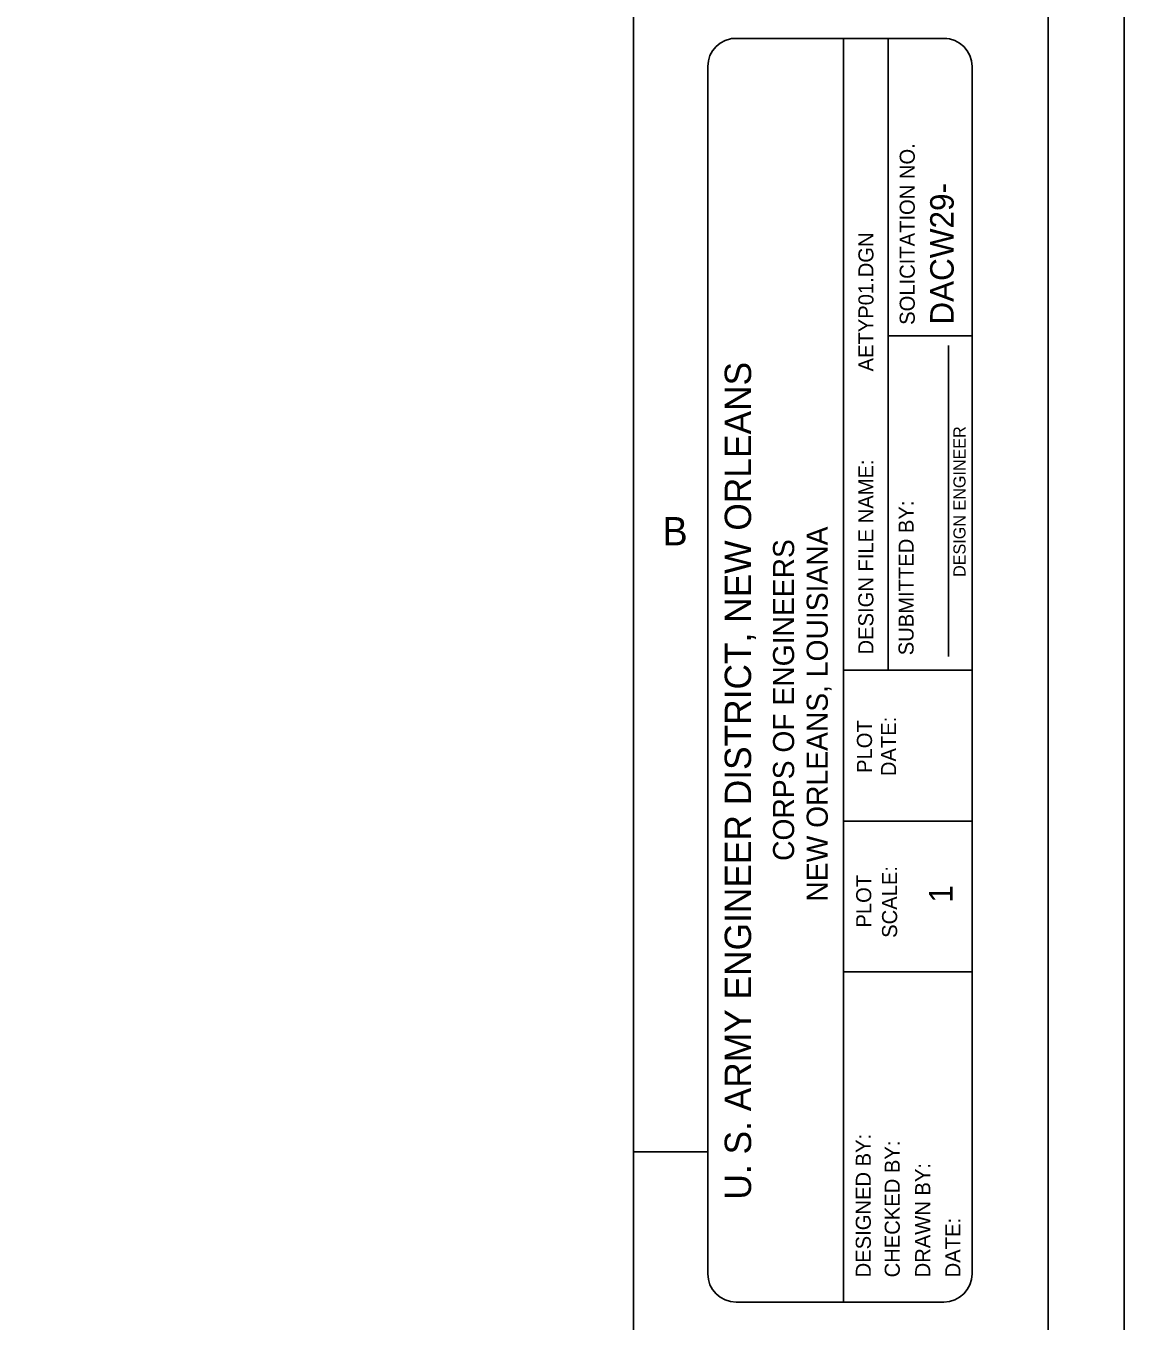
# Model space of a CAD drawing. Extents: x 44742.55 to 44745.38, y 44738.95 to 44741.13.
# Drawn here: x 44744.913 to 44745.38, y 44739.437 to 44739.989 of the extents above; entities that cross this region are included whole.
import ezdxf

# ---------------------------------------------------------------- set-up
doc = ezdxf.new("R2010")
doc.units = 0
for name, color, linetype in [('Level 1', 7, 'Continuous'), ('Level 10', 7, 'Continuous'), ('Level 2', 7, 'Continuous'), ('Level 7', 7, 'Continuous'), ('Level 9', 7, 'Continuous')]:
    doc.layers.add(name, color=color, linetype=linetype)

msp = doc.modelspace()

# ---------------------------------------------------------------- linework, layer by layer
at = {"layer": 'Level 1'}
for p, q in [((44745.30484, 44739.98338), (44745.21308, 44739.98338)), ((44745.26089, 44739.98338), (44745.26089, 44739.44515))]:
    msp.add_line(p, q, dxfattribs=at)
msp.add_lwpolyline([(44742.55302, 44741.13232), (44745.38041, 44741.13232), (44745.38041, 44738.94702), (44742.55302, 44738.94702)], close=True, dxfattribs=at)
for points in [[(44745.30359, 44739.98338), (44745.21511, 44739.98338)], [(44745.20306, 44739.4572), (44745.20306, 44739.97133)], [(44745.31564, 44739.4572), (44745.31564, 44739.97133)], [(44745.21511, 44739.44515), (44745.30359, 44739.44515)]]:
    msp.add_lwpolyline(points, dxfattribs=at)
for centre, start, end in [((44745.21511, 44739.97133), 90, 180), ((44745.30359, 44739.97133), 0, 90), ((44745.21511, 44739.4572), 180, 270), ((44745.30359, 44739.4572), 270, 0)]:
    msp.add_arc(centre, 0.01205, start, end, dxfattribs=at)
at = {"layer": 'Level 10'}
msp.add_line((44745.17144, 44739.50915), (44745.20306, 44739.50915), dxfattribs=at)
at = {"layer": 'Level 2'}
for p, q in [((44745.27984, 44739.98338), (44745.27984, 44739.71427)), ((44745.31564, 44739.85669), (44745.27984, 44739.85669)), ((44745.30561, 44739.7201), (44745.30561, 44739.85255)), ((44745.31564, 44739.71427), (44745.26089, 44739.71427)), ((44745.31564, 44739.65001), (44745.26089, 44739.65001)), ((44745.31564, 44739.58575), (44745.26089, 44739.58575))]:
    msp.add_line(p, q, dxfattribs=at)
at = {"layer": 'Level 9'}
msp.add_line((44745.34803, 44738.97941), (44745.34803, 44741.09993), dxfattribs=at)
msp.add_lwpolyline([(44745.17144, 44738.97941), (44745.17144, 44741.09993)], dxfattribs=at)

# ---------------------------------------------------------------- texts
at = {"layer": 'Level 1'}
for s, height, p in [('SOLICITATION NO.', 0.0064263, (44745.29124, 44739.86137)), ('AETYP01.DGN', 0.0064258, (44745.27364, 44739.84151)), ('U. S. ARMY ENGINEER DISTRICT, NEW ORLEANS', 0.0112451, (44745.22152, 44739.48882)), ('DESIGN ENGINEER', 0.0051401, (44745.31285, 44739.75401)), ('DESIGN FILE NAME:', 0.0064263, (44745.27362, 44739.72097)), ('SUBMITTED BY:', 0.0064263, (44745.29075, 44739.72064)), ('PLOT', 0.006426, (44745.27302, 44739.67052)), ('DATE:', 0.006426, (44745.28328, 44739.66917)), ('PLOT', 0.006426, (44745.27271, 44739.60465)), ('SCALE:', 0.006426, (44745.28372, 44739.60029)), ('DESIGNED BY:', 0.0064263, (44745.27252, 44739.45568)), ('CHECKED BY:', 0.0064263, (44745.28486, 44739.45568)), ('DRAWN BY:', 0.006426, (44745.29783, 44739.45568)), ('DATE:', 0.006426, (44745.31067, 44739.45568))]:
    msp.add_text(s, height=height, rotation=90, dxfattribs=at).set_placement(p)
msp.add_text('B', height=0.01203, dxfattribs=at).set_placement((44745.18378, 44739.76747))
at = {"layer": 'Level 7'}
for s, height, p in [('DACW29-', 0.010024, (44745.30782, 44739.86145)), ('NEW ORLEANS, LOUISIANA', 0.0089961, (44745.25418, 44739.61572)), ('CORPS OF ENGINEERS', 0.0089961, (44745.23985, 44739.63305)), ('1', 0.01002, (44745.30739, 44739.61525))]:
    msp.add_text(s, height=height, rotation=90, dxfattribs=at).set_placement(p)

doc.saveas('drawing.dxf')
